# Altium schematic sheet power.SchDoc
size A3
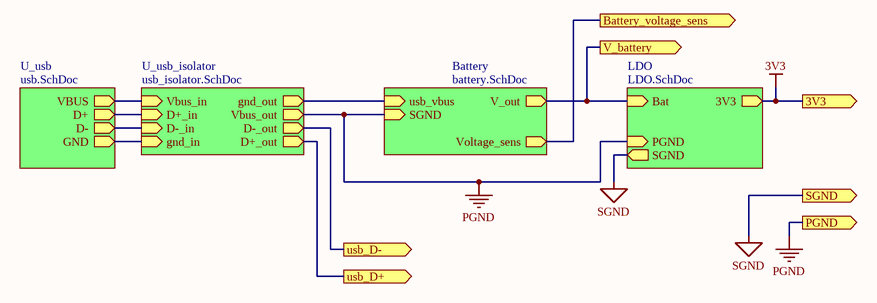
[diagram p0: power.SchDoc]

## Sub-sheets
Battery = battery.SchDoc: V_out (out), Voltage_sens (out), usb_vbus (in), SGND (in)
LDO = LDO.SchDoc: Bat (in), PGND (in), 3V3 (out), SGND (out)
U_usb = usb.SchDoc: VBUS (out), GND (out), D+ (out), D- (out)
U_usb_isolator = usb_isolator.SchDoc: Vbus_in (in), D+_in (in), D-_in (in), gnd_in (in), gnd_out (out), D-_out (out), D+_out (out), Vbus_out (out)

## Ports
3V3 (out), Battery_voltage_sens (out), PGND (out), SGND (out), usb_D+ (out), usb_D- (out), V_battery (out)

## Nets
3V3: port 3V3, sheet LDO/3V3
PGND: port PGND, sheet LDO/PGND, sheet Battery/SGND, sheet U_usb_isolator/Vbus_out
SGND: port SGND, sheet LDO/SGND
Battery_voltage_sens: port Battery_voltage_sens, sheet Battery/Voltage_sens
usb_D+: port usb_D+, sheet U_usb_isolator/D+_out
usb_D-: port usb_D-, sheet U_usb_isolator/D-_out
V_battery: port V_battery, sheet LDO/Bat, sheet Battery/V_out
(unnamed): sheet Battery/usb_vbus, sheet U_usb_isolator/gnd_out
(unnamed): sheet U_usb/VBUS, sheet U_usb_isolator/Vbus_in  [a separate net that carries the same name]
(unnamed): sheet U_usb/GND, sheet U_usb_isolator/gnd_in  [a separate net that carries the same name]
(unnamed): sheet U_usb/D+, sheet U_usb_isolator/D+_in  [a separate net that carries the same name]
(unnamed): sheet U_usb/D-, sheet U_usb_isolator/D-_in  [a separate net that carries the same name]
